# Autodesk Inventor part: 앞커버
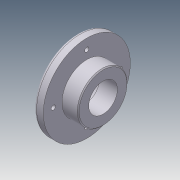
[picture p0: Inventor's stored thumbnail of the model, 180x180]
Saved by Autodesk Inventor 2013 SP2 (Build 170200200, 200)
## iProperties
Company: 한국ATC센터
Created: 2014-11
Part Number: 앞커버
Document SubType Name: Modeling
Designer: KYOUNG IL JANG
Density: 2.71 g/cm^3
Material: 알루미늄-6061
Mass: 204.895 g
Surface Area: 201.401 cm^2
Volume: 75.6071 cm^3
Author: KYOUNG IL JANG
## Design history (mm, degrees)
sketch "스케치1"
  geometry: L1 (-13.5, 0)-(13.5, 0); L2 (-13.5, 0)-(-13.5, 45.5); L3 (-13.5, 45.5)-(-3.5, 45.5); L4 (-3.5, 45.5)-(-3.5, 26); L5 (-3.5, 26)-(13.5, 26); L6 (13.5, 26)-(13.5, 0); 2 further points
  constraints: 12 end point, 3 parallel, 2 perpendicular, 1 coincident, 1 horizontal, 1 midpoint
  dimensions: "d0" = 27 distance of L1.start L1.end; "d1" = 91 diameter of L3 L1; "d2" = 52 diameter of L5 L1; "d3" = 10 distance of L2.end L3.end
revolve "회전1" sketch "스케치1" stored, may be unused: angle "d4" = 90 deg
hole "구멍1" diameter "d7" = 30; stored, may be unused: countersink angle "d11" = 90 deg, drill point angle "d13" = 118 deg; dims "d5" = 10, "d6" = 10, "d8" = 6, "d9" = 40, "d10" = 8.3, "d12" = 8
sketch "스케치2"
  geometry: 2 further points
  constraints: 1 vertical alignment
  dimensions: "d14" = 35 distance of point (0, 0) point (0, 35)
hole "구멍2" sketch "스케치2" at (0, 35) diameter "d15" = 4.5; stored, may be unused: countersink angle "d19" = 90 deg, drill point angle "d21" = 118 deg; dims "d16" = 6, "d17" = 8, "d18" = 4.4, "d20" = 8
chamfer "모따기1" distance "d25" = 0.8; stored, may be unused: second distance "d26" = 2, angle "d27" = 30 deg
fillet "모깎기1" dims "d28" = 0.3, "d29" = 3
chamfer "모따기2" distance "d30" = 1; stored, may be unused: second distance "d31" = 2, angle "d32" = 30 deg
node "솔리드1"
pattern_circular "원형 패턴1" dims angle "d23" = 360 deg
